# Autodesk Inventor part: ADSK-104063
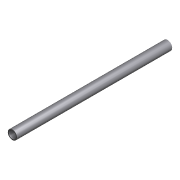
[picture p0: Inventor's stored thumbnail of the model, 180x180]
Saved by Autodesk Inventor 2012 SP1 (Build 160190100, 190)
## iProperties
Shininess: 0.0
Created: 2001-01
Part Number: ADSK-104063
Document SubType Name: Modeling
Stock Number: ADSK-104063
Density: 1 g/cm^3
Material: Default
Density: 0.0
Volumn: 0.0
Area: 0.0
PropertySet Name: Model Information
Control State: 0
Master: False
Checked Out: False
Author: gao
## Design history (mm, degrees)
node "Extrusion1" dims "d2" = 203.2, "d3" = 0
  sketch "Sketch1"
    geometry: C1 r 4.763 at (0, 0); C2 r 6.032 at (0, 0)
    constraints: 2 centre point, 1 coincident
    dimensions: "d0" = 12.065 diameter of C2; "d1" = 9.525 diameter of C1
node "Extrusion2" dims "d5" = 25.4, "d6" = 0
  sketch "Sketch2"
    geometry: C1 r 6.032 at (0, 0) reference; C2 r 6.02 at (0, 0)
    constraints: 1 centre point, 1 coincident
    dimensions: "d4" = 12.0396 diameter of C2
body "Solid1"
